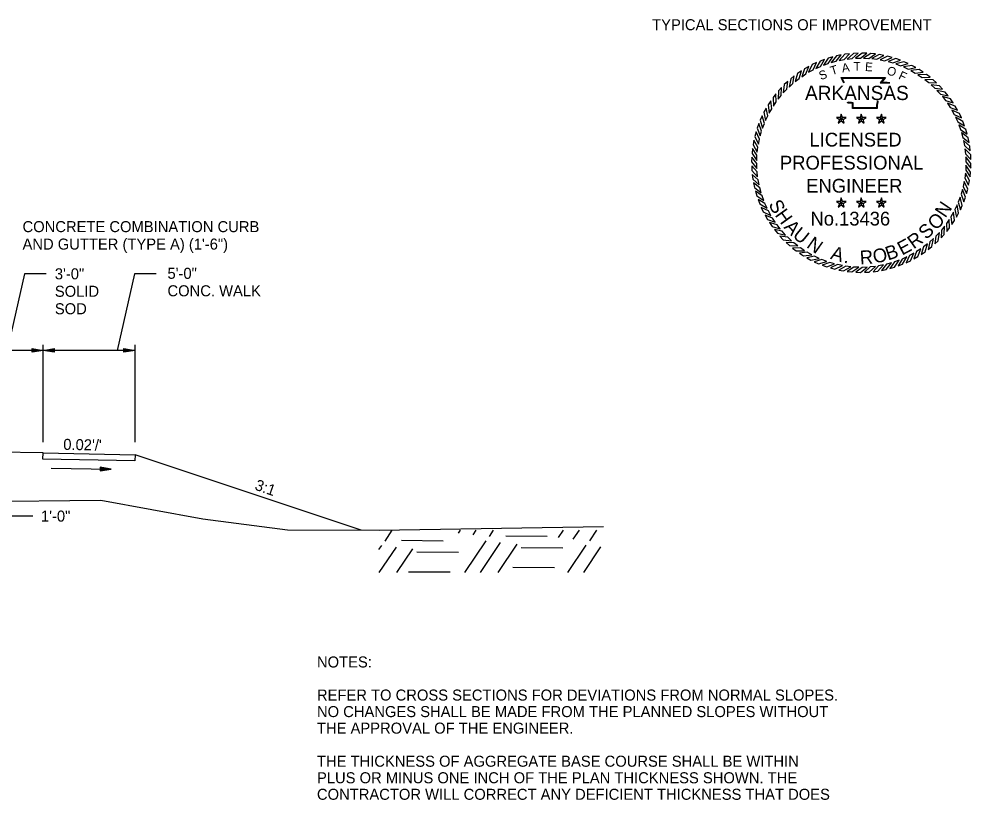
# Model space of a CAD drawing. Extents: x 1001270 to 1003428, y 1840152 to 1842912.
# Drawn here: x 1003376.7 to 1003428.5, y 1842854.8 to 1842897.3 of the extents above; entities that cross this region are included whole.
import ezdxf

# ---------------------------------------------------------------- set-up
doc = ezdxf.new("R2010")
doc.units = 0
for name, color, linetype in [('1', 7, 'Continuous'), ('19', 7, 'Continuous'), ('20', 7, 'Continuous'), ('8', 7, 'Continuous'), ('G-ANNO-SYMB', 7, 'Continuous')]:
    doc.layers.add(name, color=color, linetype=linetype)

# ---------------------------------------------------------------- blocks, each defined once
blk = doc.blocks.new('TM')
at = {"layer": '8'}
for p, q in [((-120.309, 21.181), (-119.787, -20.829)), ((0, 0), (-120.309, 21.181)), ((-31.382, 2.945), (-120.176, 10.512)), ((-119.787, -20.829), (0, 0)), ((-119.911, -10.826), (-31.307, -3.057))]:
    blk.add_line(p, q, dxfattribs=at)

msp = doc.modelspace()

# ---------------------------------------------------------------- linework, layer by layer
at = {"layer": '19'}
for p, q in [((1003376.999, 1842883.464), (1003376.042, 1842879.307)), ((1003378.177, 1842883.464), (1003376.999, 1842883.464)), ((1003382.981, 1842883.464), (1003382.024, 1842879.307)), ((1003384.16, 1842883.464), (1003382.981, 1842883.464)), ((1003378.004, 1842874.316), (1003378.004, 1842879.607)), ((1003383.004, 1842874.316), (1003383.004, 1842879.607)), ((1003383.004, 1842879.307), (1003373.504, 1842879.307)), ((1003377.404, 1842879.202), (1003377.404, 1842879.412)), ((1003377.404, 1842879.412), (1003378.004, 1842879.307)), ((1003377.404, 1842879.357), (1003377.844, 1842879.322)), ((1003378.004, 1842879.307), (1003377.404, 1842879.202)), ((1003377.844, 1842879.292), (1003377.404, 1842879.252)), ((1003378.004, 1842879.307), (1003378.604, 1842879.412)), ((1003378.604, 1842879.202), (1003378.004, 1842879.307)), ((1003378.164, 1842879.322), (1003378.604, 1842879.357)), ((1003378.604, 1842879.252), (1003378.164, 1842879.292)), ((1003378.604, 1842879.412), (1003378.604, 1842879.202)), ((1003382.404, 1842879.202), (1003382.404, 1842879.412)), ((1003382.404, 1842879.412), (1003383.004, 1842879.307)), ((1003382.404, 1842879.357), (1003382.844, 1842879.322)), ((1003383.004, 1842879.307), (1003382.404, 1842879.202)), ((1003382.844, 1842879.292), (1003382.404, 1842879.252)), ((1003378.005, 1842873.723), (1003375.004, 1842873.783)), ((1003377.991, 1842873.39), (1003378.005, 1842873.723)), ((1003378.005, 1842873.723), (1003383.004, 1842873.623)), ((1003378.005, 1842873.723), (1003378.005, 1842873.723)), ((1003383.004, 1842873.623), (1003382.99, 1842873.29)), ((1003395.305, 1842869.522), (1003383.004, 1842873.623)), ((1003382.99, 1842873.29), (1003377.991, 1842873.39)), ((1003376.004, 1842870.297), (1003377.452, 1842870.297)), ((1003376.004, 1842870.297), (1003377.452, 1842870.297)), ((1003396.612, 1842868.933), (1003397.003, 1842869.516)), ((1003400.597, 1842869.367), (1003400.703, 1842869.517)), ((1003401.392, 1842869.275), (1003401.558, 1842869.519)), ((1003402.287, 1842869.183), (1003402.513, 1842869.522)), ((1003406.051, 1842869.127), (1003406.313, 1842869.523)), ((1003406.846, 1842869.035), (1003407.178, 1842869.524)), ((1003407.741, 1842868.943), (1003408.122, 1842869.517)), ((1003397.5, 1842868.972), (1003399.76, 1842868.95)), ((1003400.949, 1842867.22), (1003402.101, 1842868.941)), ((1003401.804, 1842867.222), (1003402.896, 1842868.849)), ((1003402.759, 1842867.224), (1003403.791, 1842868.757)), ((1003403.175, 1842869.212), (1003405.435, 1842869.201)), ((1003396.272, 1842868.465), (1003396.426, 1842868.69)), ((1003396.294, 1842867.216), (1003397.221, 1842868.599)), ((1003397.249, 1842867.218), (1003398.116, 1842868.506)), ((1003398.34, 1842868.343), (1003400.6, 1842868.321)), ((1003404.005, 1842868.584), (1003406.275, 1842868.571)), ((1003406.559, 1842867.225), (1003407.555, 1842868.701)), ((1003407.414, 1842867.228), (1003408.35, 1842868.609)), ((1003397.887, 1842867.263), (1003400.158, 1842867.251)), ((1003403.563, 1842867.514), (1003405.822, 1842867.492))]:
    msp.add_line(p, q, dxfattribs=at)
for points in [[(1003313.324, 1842878.834), (1003317.014, 1842878.61), (1003321.197, 1842877.959), (1003324.919, 1842876.727), (1003334.161, 1842873.328), (1003336.64, 1842872.506), (1003341.254, 1842871.146), (1003346.806, 1842871.391), (1003355.534, 1842871.319), (1003359.358, 1842871.342), (1003368.232, 1842871.015), (1003374.396, 1842871.084), (1003381.148, 1842871.148), (1003386.685, 1842870.145), (1003391.3, 1842869.551), (1003396.285, 1842869.516)], [(1003396.285, 1842869.516), (1003408.49, 1842869.719)]]:
    msp.add_lwpolyline(points, dxfattribs=at)
at = {"layer": '20'}
msp.add_line((1003378.442, 1842872.903), (1003381.712, 1842872.838), dxfattribs=at)
at = {"layer": 'G-ANNO-SYMB'}
for points in [[(1003420.96, 1842895.277), (1003420.714, 1842895.205), (1003420.458, 1842894.826), (1003420.719, 1842894.92)], [(1003421.416, 1842895.382), (1003421.165, 1842895.329), (1003420.881, 1842894.971), (1003421.148, 1842895.045)], [(1003421.88, 1842895.45), (1003421.625, 1842895.417), (1003421.314, 1842895.083), (1003421.586, 1842895.135)], [(1003422.347, 1842895.482), (1003422.091, 1842895.469), (1003421.754, 1842895.16), (1003422.029, 1842895.191)], [(1003422.816, 1842895.477), (1003422.559, 1842895.484), (1003422.199, 1842895.203), (1003422.476, 1842895.212)], [(1003423.282, 1842895.435), (1003423.027, 1842895.463), (1003422.646, 1842895.21), (1003422.923, 1842895.197)], [(1003423.744, 1842895.357), (1003423.492, 1842895.404), (1003423.092, 1842895.183), (1003423.367, 1842895.148)], [(1003424.198, 1842895.243), (1003423.951, 1842895.31), (1003423.535, 1842895.12), (1003423.806, 1842895.064)], [(1003424.642, 1842895.093), (1003424.401, 1842895.18), (1003423.971, 1842895.023), (1003424.237, 1842894.946)], [(1003419.658, 1842894.755), (1003419.436, 1842894.627), (1003419.276, 1842894.199), (1003419.507, 1842894.351)], [(1003420.078, 1842894.963), (1003419.846, 1842894.853), (1003419.653, 1842894.438), (1003419.896, 1842894.572)], [(1003420.513, 1842895.137), (1003420.273, 1842895.046), (1003420.048, 1842894.648), (1003420.3, 1842894.762)], [(1003425.073, 1842894.909), (1003424.839, 1842895.014), (1003424.398, 1842894.892), (1003424.658, 1842894.794)], [(1003425.488, 1842894.692), (1003425.263, 1842894.815), (1003424.814, 1842894.728), (1003425.065, 1842894.61)], [(1003418.874, 1842894.243), (1003418.675, 1842894.082), (1003418.584, 1842893.634), (1003418.789, 1842893.82)], [(1003419.256, 1842894.514), (1003419.045, 1842894.369), (1003418.919, 1842893.93), (1003419.138, 1842894.1)], [(1003425.885, 1842894.443), (1003425.67, 1842894.584), (1003425.216, 1842894.532), (1003425.457, 1842894.395)], [(1003426.261, 1842894.164), (1003426.058, 1842894.321), (1003425.601, 1842894.305), (1003425.83, 1842894.149)], [(1003418.18, 1842893.615), (1003418.008, 1842893.425), (1003417.988, 1842892.968), (1003418.161, 1842893.184)], [(1003418.515, 1842893.942), (1003418.329, 1842893.766), (1003418.273, 1842893.312), (1003418.462, 1842893.515)], [(1003426.614, 1842893.856), (1003426.424, 1842894.028), (1003425.967, 1842894.048), (1003426.183, 1842893.875)], [(1003426.942, 1842893.521), (1003426.765, 1842893.708), (1003426.312, 1842893.763), (1003426.514, 1842893.574)], [(1003417.872, 1842893.262), (1003417.716, 1842893.059), (1003417.732, 1842892.602), (1003417.887, 1842892.831)], [(1003427.242, 1842893.162), (1003427.081, 1842893.361), (1003426.633, 1842893.453), (1003426.82, 1842893.248)], [(1003427.513, 1842892.78), (1003427.368, 1842892.992), (1003426.929, 1842893.118), (1003427.099, 1842892.899)], [(1003417.593, 1842892.886), (1003417.453, 1842892.671), (1003417.504, 1842892.217), (1003417.642, 1842892.457)], [(1003427.754, 1842892.378), (1003427.626, 1842892.6), (1003427.198, 1842892.76), (1003427.35, 1842892.529)], [(1003417.127, 1842892.074), (1003417.022, 1842891.84), (1003417.144, 1842891.399), (1003417.242, 1842891.659)], [(1003417.344, 1842892.489), (1003417.221, 1842892.264), (1003417.308, 1842891.815), (1003417.426, 1842892.066)], [(1003421.427, 1842891.894), (1003421.488, 1842891.978), (1003421.427, 1842892.167), (1003421.366, 1842891.978)], [(1003422.518, 1842891.894), (1003422.579, 1842891.978), (1003422.518, 1842892.167), (1003422.456, 1842891.978)], [(1003423.609, 1842891.894), (1003423.67, 1842891.978), (1003423.609, 1842892.167), (1003423.547, 1842891.978)], [(1003427.962, 1842891.958), (1003427.852, 1842892.19), (1003427.438, 1842892.383), (1003427.571, 1842892.14)], [(1003416.943, 1842891.643), (1003416.857, 1842891.401), (1003417.013, 1842890.972), (1003417.09, 1842891.238)], [(1003421.427, 1842891.894), (1003421.366, 1842891.978), (1003421.167, 1842891.978), (1003421.328, 1842891.862)], [(1003421.427, 1842891.894), (1003421.328, 1842891.862), (1003421.266, 1842891.674), (1003421.427, 1842891.79)], [(1003421.427, 1842891.894), (1003421.526, 1842891.862), (1003421.686, 1842891.978), (1003421.488, 1842891.978)], [(1003421.427, 1842891.894), (1003421.427, 1842891.79), (1003421.587, 1842891.674), (1003421.526, 1842891.862)], [(1003422.518, 1842891.894), (1003422.456, 1842891.978), (1003422.258, 1842891.978), (1003422.419, 1842891.862)], [(1003422.518, 1842891.894), (1003422.419, 1842891.862), (1003422.357, 1842891.674), (1003422.518, 1842891.79)], [(1003422.518, 1842891.894), (1003422.617, 1842891.862), (1003422.777, 1842891.978), (1003422.579, 1842891.978)], [(1003422.518, 1842891.894), (1003422.518, 1842891.79), (1003422.678, 1842891.674), (1003422.617, 1842891.862)], [(1003423.609, 1842891.894), (1003423.547, 1842891.978), (1003423.349, 1842891.978), (1003423.51, 1842891.862)], [(1003423.609, 1842891.894), (1003423.51, 1842891.862), (1003423.448, 1842891.674), (1003423.609, 1842891.79)], [(1003423.609, 1842891.894), (1003423.708, 1842891.862), (1003423.868, 1842891.978), (1003423.67, 1842891.978)], [(1003423.609, 1842891.894), (1003423.609, 1842891.79), (1003423.769, 1842891.674), (1003423.708, 1842891.862)], [(1003428.137, 1842891.524), (1003428.045, 1842891.763), (1003427.647, 1842891.988), (1003427.761, 1842891.736)], [(1003428.277, 1842891.076), (1003428.204, 1842891.323), (1003427.825, 1842891.578), (1003427.919, 1842891.318)], [(1003416.793, 1842891.199), (1003416.726, 1842890.952), (1003416.916, 1842890.535), (1003416.972, 1842890.807)], [(1003428.381, 1842890.62), (1003428.328, 1842890.871), (1003427.97, 1842891.156), (1003428.044, 1842890.888)], [(1003416.679, 1842890.745), (1003416.632, 1842890.493), (1003416.854, 1842890.093), (1003416.888, 1842890.368)], [(1003428.449, 1842890.156), (1003428.417, 1842890.411), (1003428.082, 1842890.723), (1003428.134, 1842890.45)], [(1003416.601, 1842890.283), (1003416.574, 1842890.028), (1003416.826, 1842889.647), (1003416.839, 1842889.923)], [(1003428.481, 1842889.689), (1003428.468, 1842889.945), (1003428.159, 1842890.282), (1003428.19, 1842890.007)], [(1003416.559, 1842889.816), (1003416.552, 1842889.56), (1003416.833, 1842889.2), (1003416.825, 1842889.477)], [(1003428.476, 1842889.221), (1003428.483, 1842889.477), (1003428.202, 1842889.837), (1003428.211, 1842889.56)], [(1003416.554, 1842889.348), (1003416.567, 1842889.092), (1003416.876, 1842888.755), (1003416.845, 1842889.03)], [(1003428.356, 1842888.292), (1003428.404, 1842888.544), (1003428.182, 1842888.944), (1003428.147, 1842888.669)], [(1003428.434, 1842888.754), (1003428.462, 1842889.009), (1003428.209, 1842889.39), (1003428.196, 1842889.114)], [(1003416.586, 1842888.881), (1003416.619, 1842888.626), (1003416.953, 1842888.314), (1003416.901, 1842888.587)], [(1003416.654, 1842888.417), (1003416.707, 1842888.166), (1003417.065, 1842887.881), (1003416.992, 1842888.149)], [(1003428.242, 1842887.838), (1003428.309, 1842888.086), (1003428.119, 1842888.502), (1003428.063, 1842888.23)], [(1003416.759, 1842887.961), (1003416.831, 1842887.714), (1003417.21, 1842887.459), (1003417.116, 1842887.719)], [(1003428.092, 1842887.394), (1003428.179, 1842887.636), (1003428.022, 1842888.065), (1003427.945, 1842887.799)], [(1003416.899, 1842887.514), (1003416.99, 1842887.274), (1003417.388, 1842887.049), (1003417.274, 1842887.301)], [(1003421.427, 1842887.326), (1003421.366, 1842887.41), (1003421.167, 1842887.41), (1003421.328, 1842887.294)], [(1003421.427, 1842887.326), (1003421.488, 1842887.41), (1003421.427, 1842887.599), (1003421.366, 1842887.41)], [(1003421.427, 1842887.326), (1003421.526, 1842887.294), (1003421.686, 1842887.41), (1003421.488, 1842887.41)], [(1003422.518, 1842887.326), (1003422.456, 1842887.41), (1003422.258, 1842887.41), (1003422.419, 1842887.294)], [(1003422.518, 1842887.326), (1003422.579, 1842887.41), (1003422.518, 1842887.599), (1003422.456, 1842887.41)], [(1003422.518, 1842887.326), (1003422.617, 1842887.294), (1003422.777, 1842887.41), (1003422.579, 1842887.41)], [(1003423.609, 1842887.326), (1003423.547, 1842887.41), (1003423.349, 1842887.41), (1003423.51, 1842887.294)], [(1003423.609, 1842887.326), (1003423.67, 1842887.41), (1003423.609, 1842887.599), (1003423.547, 1842887.41)], [(1003423.609, 1842887.326), (1003423.708, 1842887.294), (1003423.868, 1842887.41), (1003423.67, 1842887.41)], [(1003427.909, 1842886.963), (1003428.013, 1842887.197), (1003427.891, 1842887.638), (1003427.793, 1842887.379)], [(1003417.073, 1842887.079), (1003417.183, 1842886.847), (1003417.598, 1842886.654), (1003417.464, 1842886.897)], [(1003421.427, 1842887.326), (1003421.328, 1842887.294), (1003421.266, 1842887.105), (1003421.427, 1842887.222)], [(1003421.427, 1842887.326), (1003421.427, 1842887.222), (1003421.587, 1842887.105), (1003421.526, 1842887.294)], [(1003422.518, 1842887.326), (1003422.419, 1842887.294), (1003422.357, 1842887.105), (1003422.518, 1842887.222)], [(1003422.518, 1842887.326), (1003422.518, 1842887.222), (1003422.678, 1842887.105), (1003422.617, 1842887.294)], [(1003423.609, 1842887.326), (1003423.51, 1842887.294), (1003423.448, 1842887.105), (1003423.609, 1842887.222)], [(1003423.609, 1842887.326), (1003423.609, 1842887.222), (1003423.769, 1842887.105), (1003423.708, 1842887.294)], [(1003427.691, 1842886.548), (1003427.814, 1842886.773), (1003427.727, 1842887.222), (1003427.609, 1842886.971)], [(1003417.282, 1842886.659), (1003417.409, 1842886.437), (1003417.838, 1842886.277), (1003417.685, 1842886.508)], [(1003427.163, 1842885.775), (1003427.32, 1842885.978), (1003427.304, 1842886.435), (1003427.148, 1842886.206)], [(1003427.442, 1842886.151), (1003427.583, 1842886.366), (1003427.531, 1842886.82), (1003427.394, 1842886.58)], [(1003417.522, 1842886.257), (1003417.667, 1842886.045), (1003418.106, 1842885.919), (1003417.936, 1842886.138)], [(1003417.793, 1842885.875), (1003417.954, 1842885.676), (1003418.402, 1842885.584), (1003418.216, 1842885.789)], [(1003426.855, 1842885.422), (1003427.027, 1842885.613), (1003427.047, 1842886.069), (1003426.874, 1842885.853)], [(1003418.094, 1842885.516), (1003418.27, 1842885.329), (1003418.724, 1842885.274), (1003418.522, 1842885.463)], [(1003426.161, 1842884.794), (1003426.361, 1842884.955), (1003426.452, 1842885.403), (1003426.247, 1842885.217)], [(1003426.52, 1842885.095), (1003426.707, 1842885.271), (1003426.763, 1842885.725), (1003426.573, 1842885.523)], [(1003418.421, 1842885.181), (1003418.612, 1842885.009), (1003419.069, 1842884.989), (1003418.852, 1842885.162)], [(1003418.774, 1842884.873), (1003418.978, 1842884.716), (1003419.435, 1842884.732), (1003419.205, 1842884.888)], [(1003425.377, 1842884.282), (1003425.599, 1842884.41), (1003425.76, 1842884.838), (1003425.528, 1842884.686)], [(1003425.779, 1842884.523), (1003425.991, 1842884.668), (1003426.117, 1842885.107), (1003425.898, 1842884.937)], [(1003419.15, 1842884.594), (1003419.365, 1842884.454), (1003419.82, 1842884.505), (1003419.579, 1842884.643)], [(1003419.547, 1842884.345), (1003419.772, 1842884.222), (1003420.221, 1842884.309), (1003419.97, 1842884.427)], [(1003424.523, 1842883.9), (1003424.762, 1842883.991), (1003424.988, 1842884.389), (1003424.735, 1842884.275)], [(1003424.957, 1842884.074), (1003425.189, 1842884.184), (1003425.382, 1842884.599), (1003425.14, 1842884.465)], [(1003419.962, 1842884.128), (1003420.196, 1842884.023), (1003420.637, 1842884.145), (1003420.378, 1842884.243)], [(1003420.393, 1842883.944), (1003420.635, 1842883.858), (1003421.064, 1842884.014), (1003420.798, 1842884.091)], [(1003420.837, 1842883.794), (1003421.085, 1842883.727), (1003421.501, 1842883.917), (1003421.229, 1842883.973)], [(1003421.291, 1842883.68), (1003421.543, 1842883.633), (1003421.943, 1842883.854), (1003421.668, 1842883.889)], [(1003421.753, 1842883.602), (1003422.008, 1842883.574), (1003422.39, 1842883.827), (1003422.113, 1842883.84)], [(1003422.22, 1842883.56), (1003422.476, 1842883.553), (1003422.837, 1842883.834), (1003422.56, 1842883.825)], [(1003422.688, 1842883.555), (1003422.944, 1842883.568), (1003423.282, 1842883.877), (1003423.006, 1842883.846)], [(1003423.156, 1842883.587), (1003423.41, 1842883.62), (1003423.722, 1842883.954), (1003423.45, 1842883.902)], [(1003423.619, 1842883.655), (1003423.87, 1842883.708), (1003424.155, 1842884.066), (1003423.887, 1842883.993)], [(1003424.076, 1842883.76), (1003424.322, 1842883.832), (1003424.577, 1842884.211), (1003424.317, 1842884.117)]]:
    msp.add_lwpolyline(points, close=True, dxfattribs=at)
for points in [[(1003421.562, 1842893.849), (1003421.423, 1842894.15), (1003423.829, 1842894.151), (1003423.628, 1842893.899), (1003423.792, 1842893.901), (1003423.928, 1842893.902), (1003424.065, 1842893.888)], [(1003421.596, 1842893.864), (1003421.482, 1842894.112), (1003423.75, 1842894.113), (1003423.548, 1842893.859), (1003423.792, 1842893.863), (1003423.926, 1842893.864), (1003424.06, 1842893.85)], [(1003423.45, 1842892.84), (1003423.409, 1842892.807), (1003423.395, 1842892.757), (1003423.382, 1842892.632), (1003423.382, 1842892.466), (1003422.038, 1842892.466), (1003422.038, 1842892.69), (1003422.038, 1842892.74), (1003421.984, 1842892.757), (1003421.793, 1842892.757), (1003421.759, 1842892.809)], [(1003423.426, 1842892.87), (1003423.375, 1842892.829), (1003423.358, 1842892.764), (1003423.344, 1842892.634), (1003423.344, 1842892.504), (1003422.077, 1842892.504), (1003422.077, 1842892.69), (1003422.077, 1842892.768), (1003421.99, 1842892.795), (1003421.813, 1842892.795), (1003421.791, 1842892.829)]]:
    msp.add_lwpolyline(points, dxfattribs=at)

# ---------------------------------------------------------------- block references
at = {"layer": '19', "xscale": 0.0050063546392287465, "yscale": 0.005006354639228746, "rotation": -1.1310771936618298}
msp.add_blockref('TM', (1003381.712, 1842872.836), dxfattribs=at)

# ---------------------------------------------------------------- texts
at = {"layer": '1'}
msp.add_text('TYPICAL SECTIONS OF IMPROVEMENT', height=0.6, dxfattribs=at).set_placement((1003411.138, 1842896.727))
msp.add_text('TYPICAL SECTIONS OF IMPROVEMENT', height=0.6, dxfattribs=at).set_placement((1003411.138, 1842896.727))
at = {"layer": '19'}
for s, p in [('CONCRETE COMBINATION CURB', (1003376.885, 1842885.74)), ('AND GUTTER (TYPE A) (1\'-6")', (1003376.885, 1842884.79)), ('3\'-0"', (1003378.643, 1842883.172)), ('5\'-0"', (1003384.771, 1842883.199)), ('SOLID ', (1003378.643, 1842882.222)), ('CONC. WALK', (1003384.771, 1842882.249)), ('SOD', (1003378.643, 1842881.272)), ('NOTES:', (1003392.903, 1842862.052)), ('REFER TO CROSS SECTIONS FOR DEVIATIONS FROM NORMAL SLOPES.', (1003392.903, 1842860.252)), ('NO CHANGES SHALL BE MADE FROM THE PLANNED SLOPES WITHOUT', (1003392.903, 1842859.352)), ('THE APPROVAL OF THE ENGINEER.', (1003392.903, 1842858.452)), ('THE THICKNESS OF AGGREGATE BASE COURSE SHALL BE WITHIN', (1003392.903, 1842856.652)), ('PLUS OR MINUS ONE INCH OF THE PLAN THICKNESS SHOWN. THE', (1003392.903, 1842855.752)), ('CONTRACTOR WILL CORRECT ANY DEFICIENT THICKNESS THAT DOES', (1003392.903, 1842854.852))]:
    msp.add_text(s, height=0.6, dxfattribs=at).set_placement(p)
for s, rotation, p in [("0.02'/'", 358.8515, (1003379.096, 1842873.896)), ('3:1', 340.4943, (1003389.476, 1842871.742)), ('1\'-0"', 360, (1003377.888, 1842869.989))]:
    msp.add_text(s, height=0.6, rotation=rotation, dxfattribs=at).set_placement(p)
at = {"layer": 'G-ANNO-SYMB'}
for s, height, rotation, p in [('T', 0.475, 16.9015, (1003420.912, 1842894.277)), ('A', 0.475, 8.6788, (1003421.489, 1842894.428)), ('T', 0.475, 1.4789, (1003422.102, 1842894.522)), ('E', 0.475, 356.672, (1003422.709, 1842894.508)), ('O', 0.475, 341.2218, (1003423.862, 1842894.345)), ('S', 0.475, 19.7726, (1003420.309, 1842894.006)), ('F', 0.475, 335.3628, (1003424.501, 1842894.095)), ('ARKANSAS', 0.7747, 360, (1003419.456, 1842892.927)), ('LICENSED', 0.75, 360, (1003419.696, 1842890.398)), ('PROFESSIONAL', 0.75, 360, (1003418.089, 1842889.144)), ('ENGINEER', 0.75, 360, (1003419.518, 1842887.889)), ('S', 0.75, 298.1636, (1003417.45, 1842887.259)), ('N', 0.75, 56.1007, (1003427.092, 1842886.475)), ('H', 0.75, 305.619, (1003417.792, 1842886.671)), ('No.13436', 0.747, 360, (1003419.754, 1842886.101)), ('O', 0.75, 44.7757, (1003426.571, 1842885.8)), ('A', 0.75, 313.4472, (1003418.268, 1842885.986)), ('U', 0.75, 320.9026, (1003418.735, 1842885.497)), ('S', 0.75, 43.4878, (1003426.055, 1842885.302)), ('N', 0.75, 324.9326, (1003419.491, 1842884.939)), ('E', 0.75, 27.8315, (1003424.732, 1842884.46)), ('R', 0.75, 35.6597, (1003425.366, 1842884.793)), ('A', 0.75, 343.0991, (1003420.799, 1842884.295)), ('O', 0.75, 11.4296, (1003423.223, 1842884.03)), ('B', 0.75, 18.885, (1003423.974, 1842884.189)), ('R', 0.75, 3.2287, (1003422.455, 1842883.982)), ('.', 0.75, 351.3, (1003421.536, 1842884.077))]:
    msp.add_text(s, height=height, rotation=rotation, dxfattribs=at).set_placement(p)

doc.saveas('drawing.dxf')
